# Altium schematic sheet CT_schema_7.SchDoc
size 368 x 245 mm
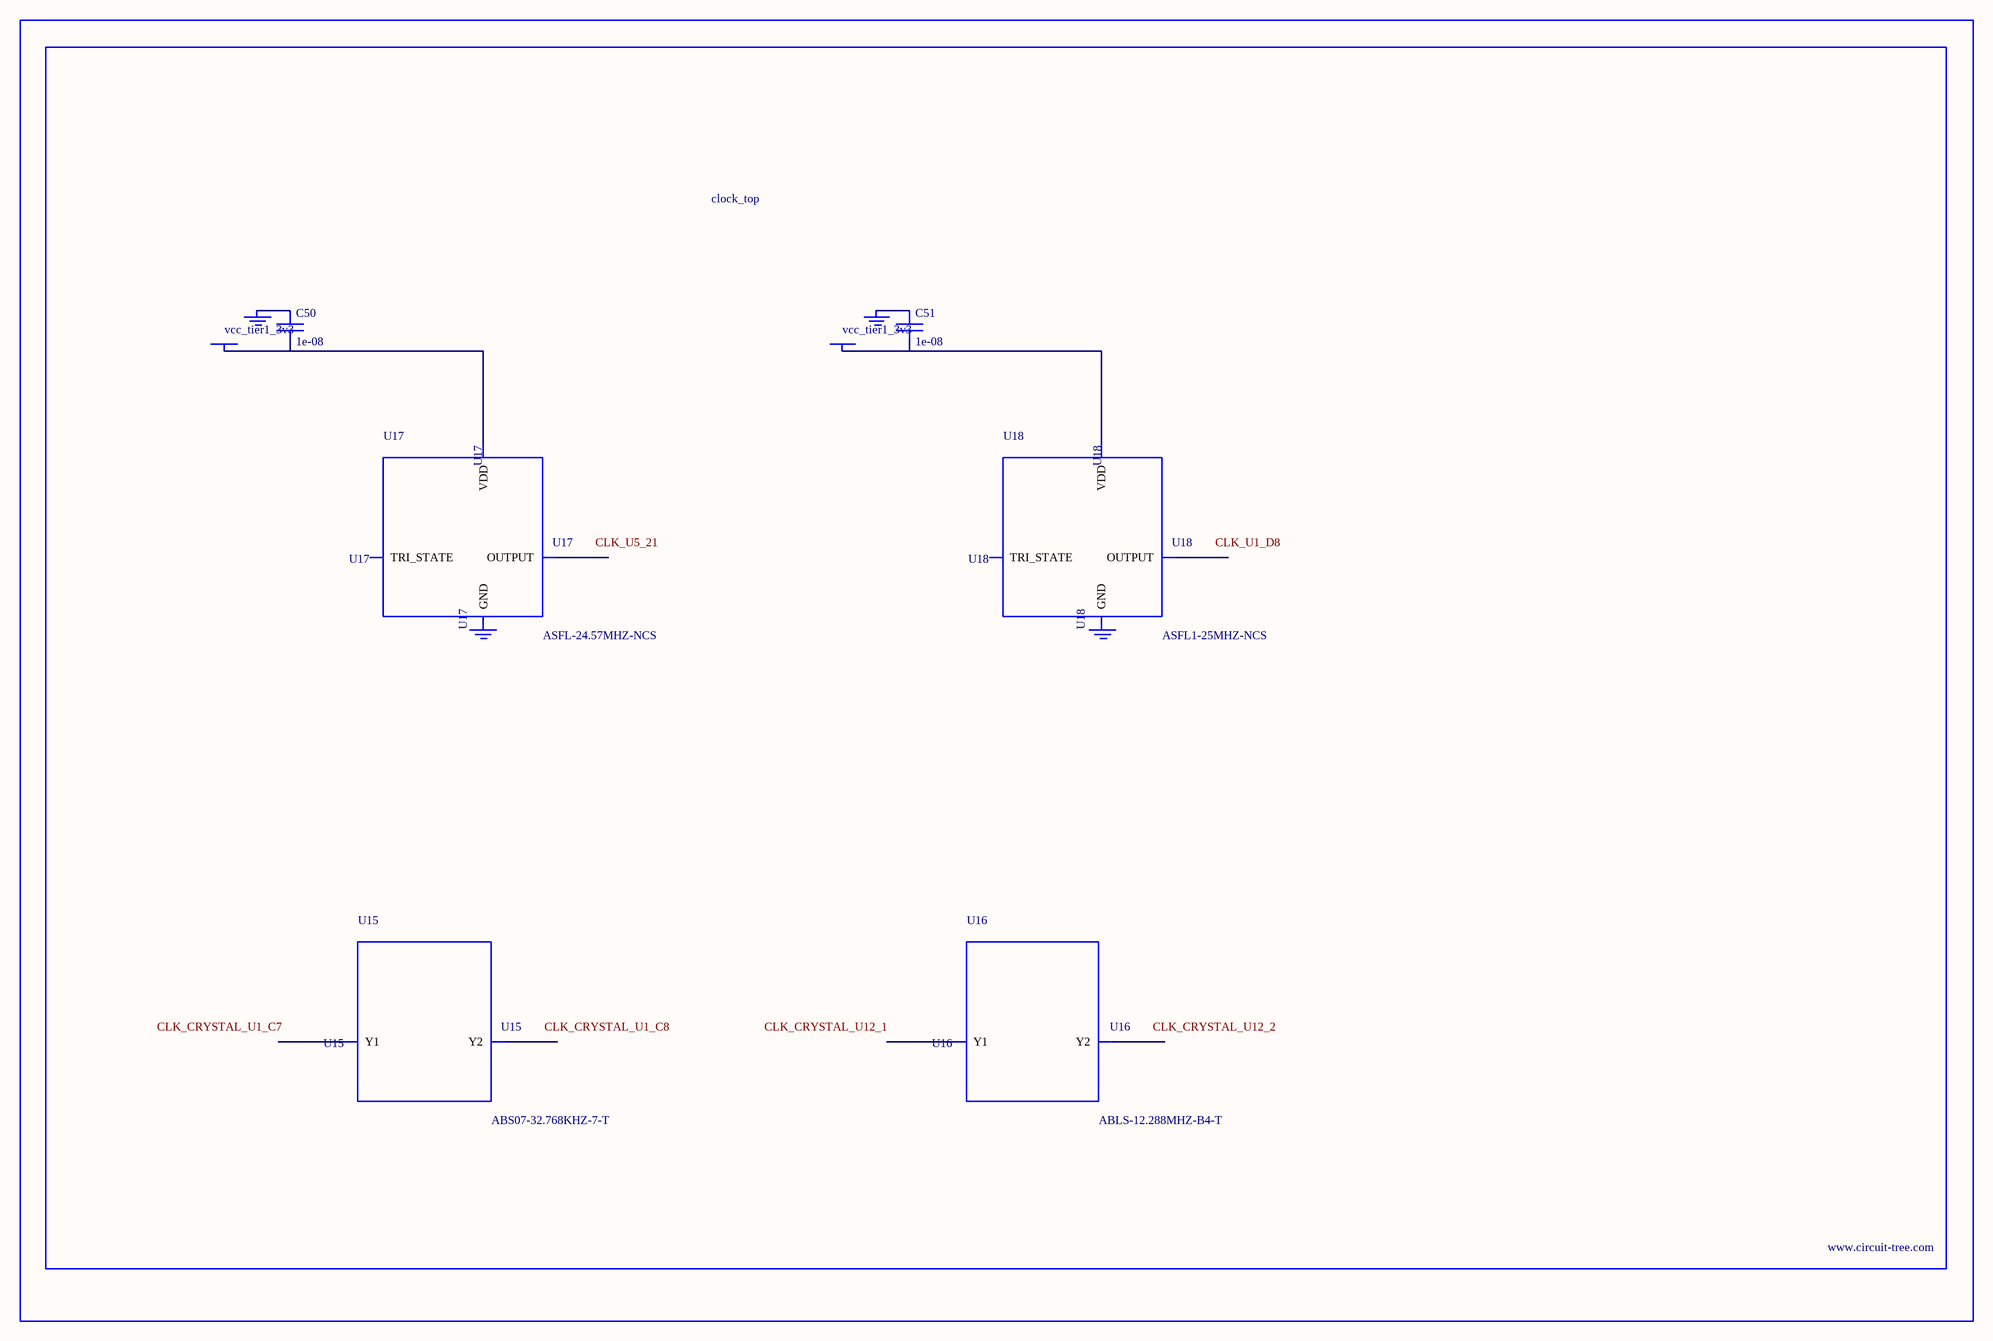
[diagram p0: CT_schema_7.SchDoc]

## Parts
BORDER6  (no value)
C50  1e-08  [C0402]
C51  1e-08  [C0402]
GND_INSTANCE_6_0  (no value)
GND_INSTANCE_6_1  (no value)
GND_INSTANCE_6_2  (no value)
GND_INSTANCE_6_3  (no value)
POWER_INSTANCE_6_0  vcc_tier1_3v3
POWER_INSTANCE_6_1  vcc_tier1_3v3
U15  ABS07-32.768KHZ-7-T  [ABS07-32.768KHZ-7-T]
U16  ABLS-12.288MHZ-B4-T  [ABLS-12.288MHZ-B4-T]
U17  ASFL-24.57MHZ-NCS  [ASFL1]
U18  ASFL1-25MHZ-NCS  [ASFL1]

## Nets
NetC50_1: C50.1 GND_INSTANCE_6_0.0(GND)
NetC50_2: C50.2 POWER_INSTANCE_6_0.0(PWR) U17.4(VDD)
NetC51_1: C51.1 GND_INSTANCE_6_2.0(GND)
NetC51_2: C51.2 POWER_INSTANCE_6_1.0(PWR) U18.4(VDD)

Not connected (* = marked no-connect by the designer): GND_INSTANCE_6_1 0(GND); GND_INSTANCE_6_3 0(GND); U15 1(Y1) 2(Y2); U16 1(Y1) 2(Y2); U17 1(TRI_STATE) 2(GND) 3(OUTPUT); U18 1(TRI_STATE) 2(GND) 3(OUTPUT)

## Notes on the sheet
- Labels drawn without touching a wire or pin: CLK_CRYSTAL_U1_C7, CLK_CRYSTAL_U1_C8, CLK_CRYSTAL_U12_1, CLK_CRYSTAL_U12_2, CLK_U1_D8, CLK_U5_21

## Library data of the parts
BORDER6 = BORDER_PAGE6
C50 C51 = C0402C103K3RAC
GND_INSTANCE_6_0-GND_INSTANCE_6_3 = GND
POWER_INSTANCE_6_0 POWER_INSTANCE_6_1 = PWR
